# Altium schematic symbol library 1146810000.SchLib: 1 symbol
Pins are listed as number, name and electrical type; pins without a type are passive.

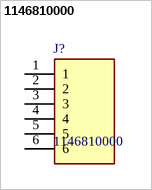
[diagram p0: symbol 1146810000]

## 1146810000
designator J?
PCB plug-in connector, male header, open side, THT solder connection, 5.08 mm, Number of poles: 6, 90, Solder pin length: 3.2 mm, tinned, orange, Box; Manufacturer_Name: Weidmuller; Geometry.Height: 8.4mm
footprint 1146810000
pins: 1, 2, 3, 4, 5, 6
